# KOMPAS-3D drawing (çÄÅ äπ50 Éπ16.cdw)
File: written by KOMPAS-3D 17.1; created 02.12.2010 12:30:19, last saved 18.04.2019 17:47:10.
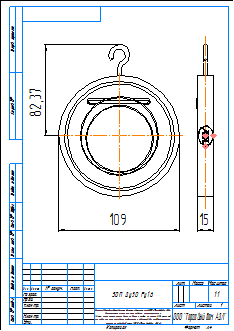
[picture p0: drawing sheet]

Sheet 1: A4, portrait

Title block, sheet 1: name: ЗОП Ду50 Ру16; material: Внимание! Данный продукт является объектом авторского права ООО «Торговый Дом АДЛ». / Запрещается изменение, копирование, распространение / (в том числе путем копирования на другие сайты и ресурсы в Интернете) / или любое иное использование информации и объектов без предварительного / согласия правообладателя (ООО «Торговый Дом АДЛ»).; scale: 1:1; sheets: 1; organisation: ООО "Торговый дом АДЛ"; sheet format: A4; stored path: \\adlc.lan\data\АДЛ_ПКД\3D-модели\ADL production\Клапаны обратные ГРАНЛОК\ЗОП\KOMPAS 2D\ЗОП Ду50 Ру16.cdw

Views: Спереди 1, Проекционный вид 2
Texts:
  bsv
  adl
Dimensions and other numbers on the sheet: 109; 15; 82,37; 1:1; 1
